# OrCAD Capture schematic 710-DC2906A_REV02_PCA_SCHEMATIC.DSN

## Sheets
1 PAGE2: company: ANALOG DEVICES; note: DEMO BOARD BILL OF MATERIALS; note: ISOLATED TRIPLE OUTPUT FLYBACK
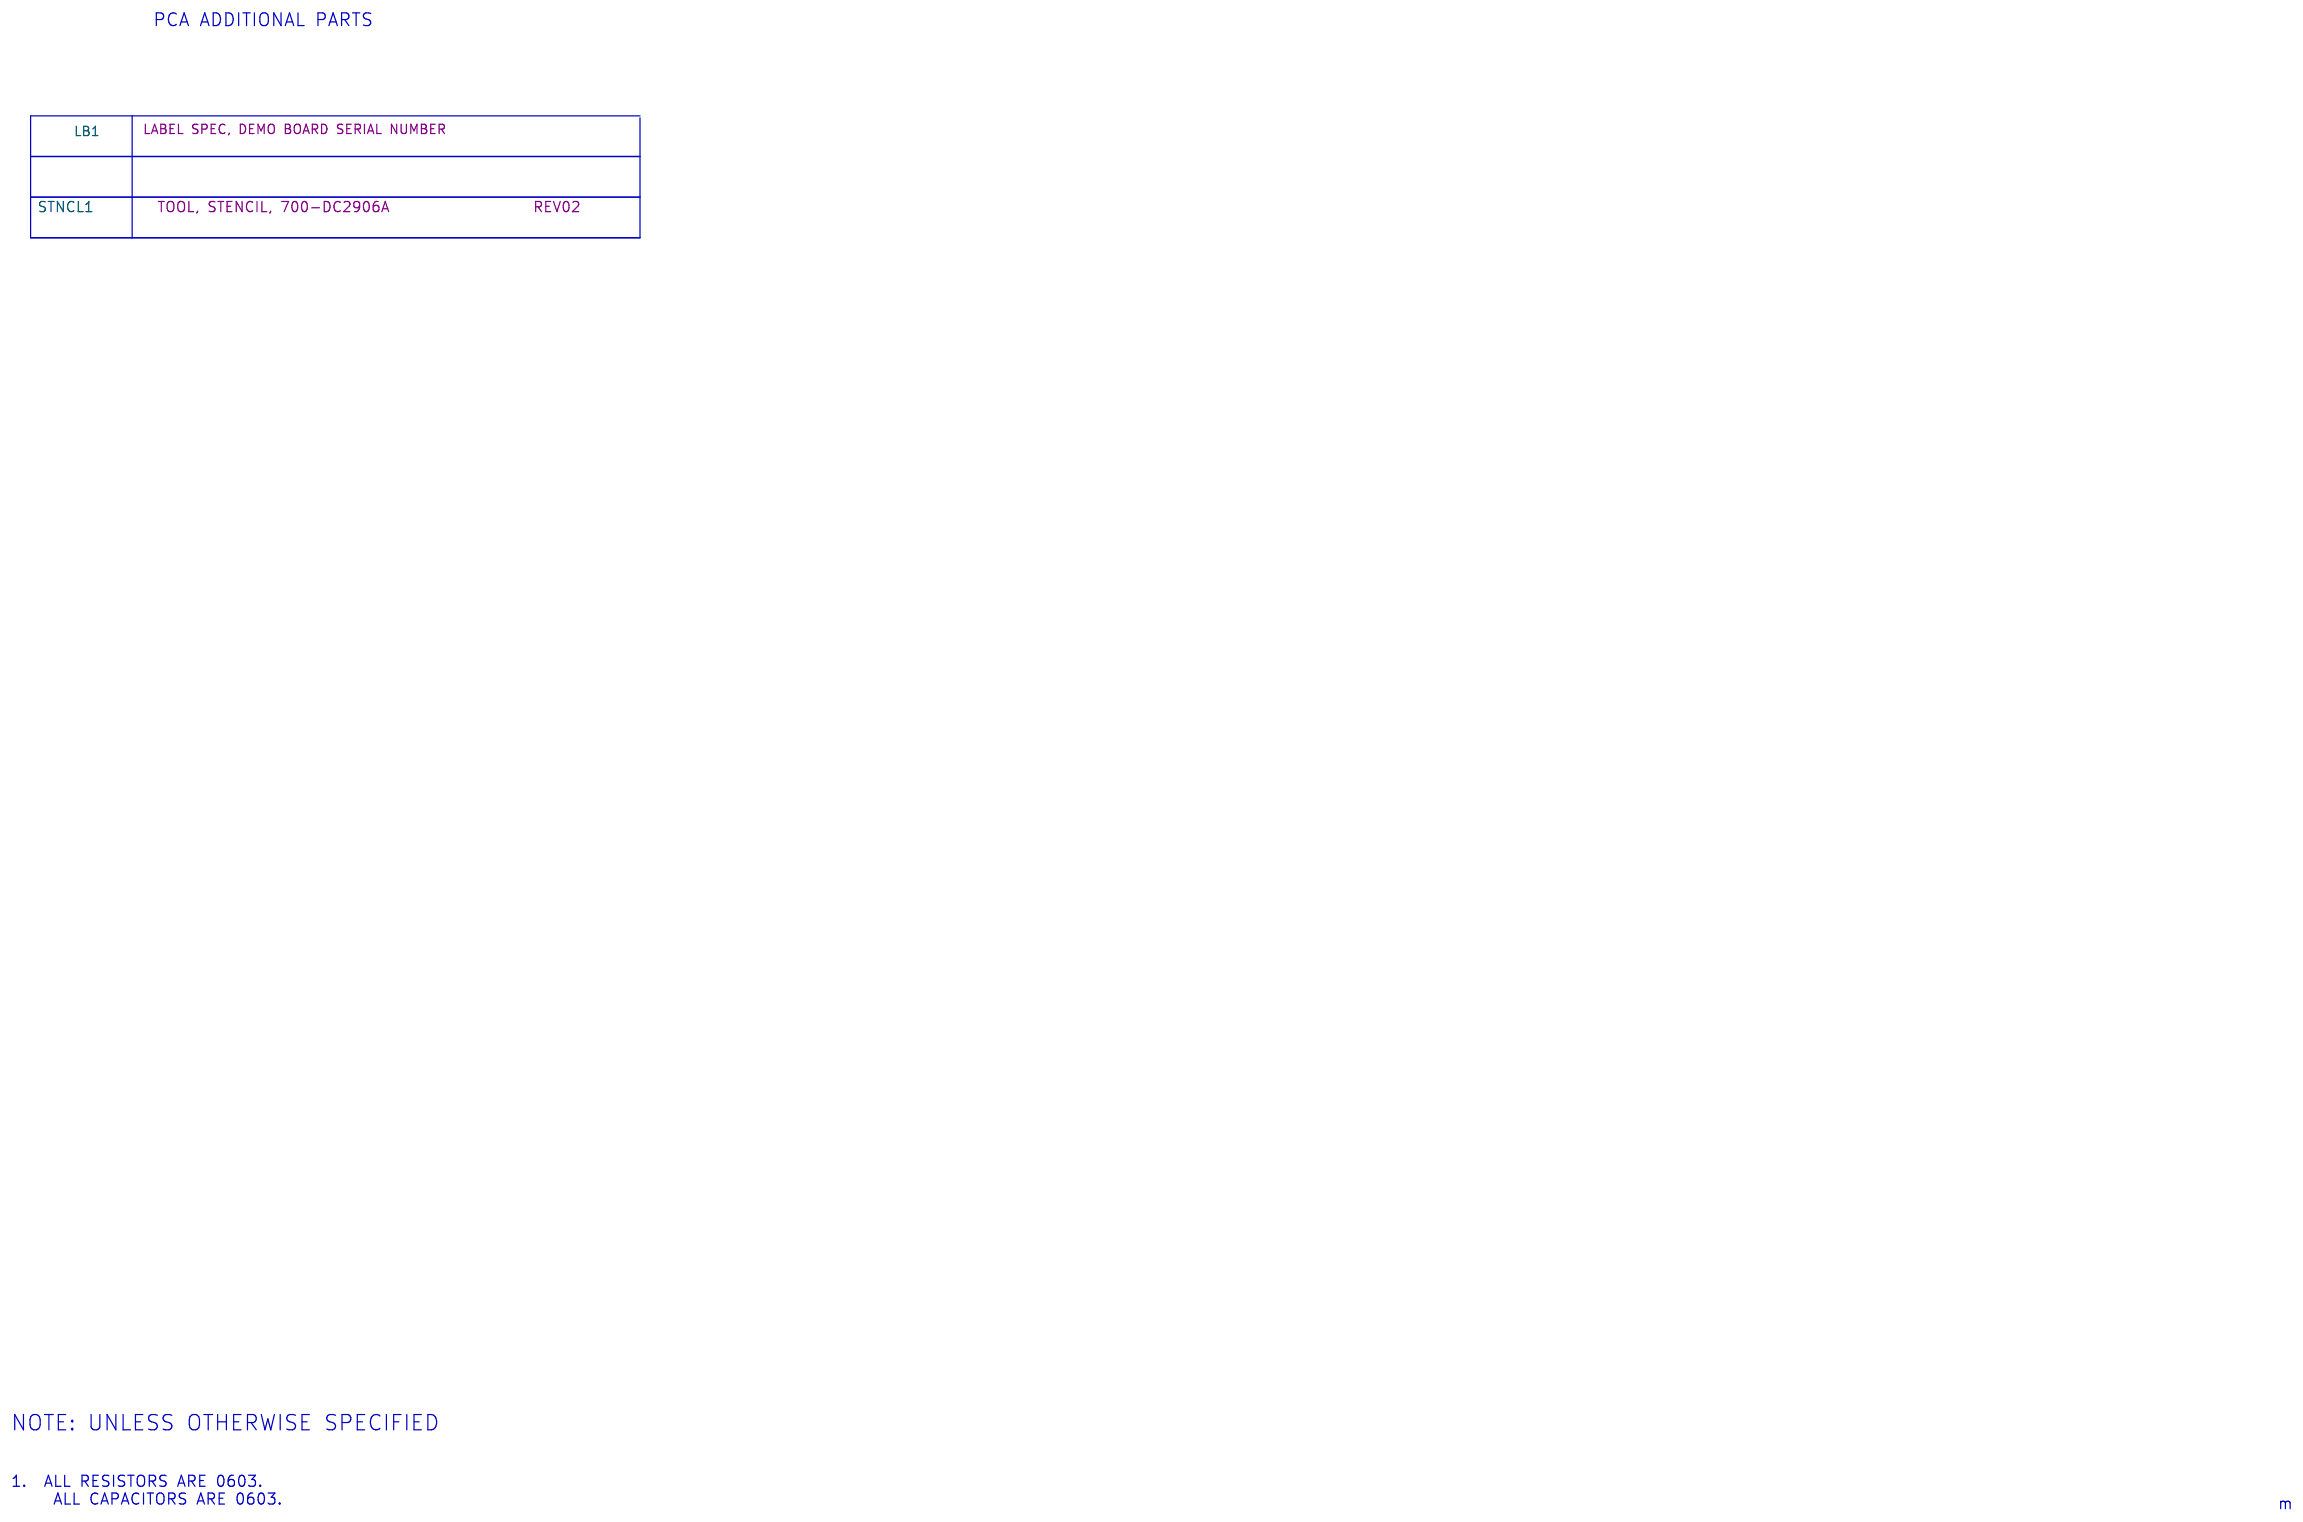
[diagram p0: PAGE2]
2 LT8302: size Custom
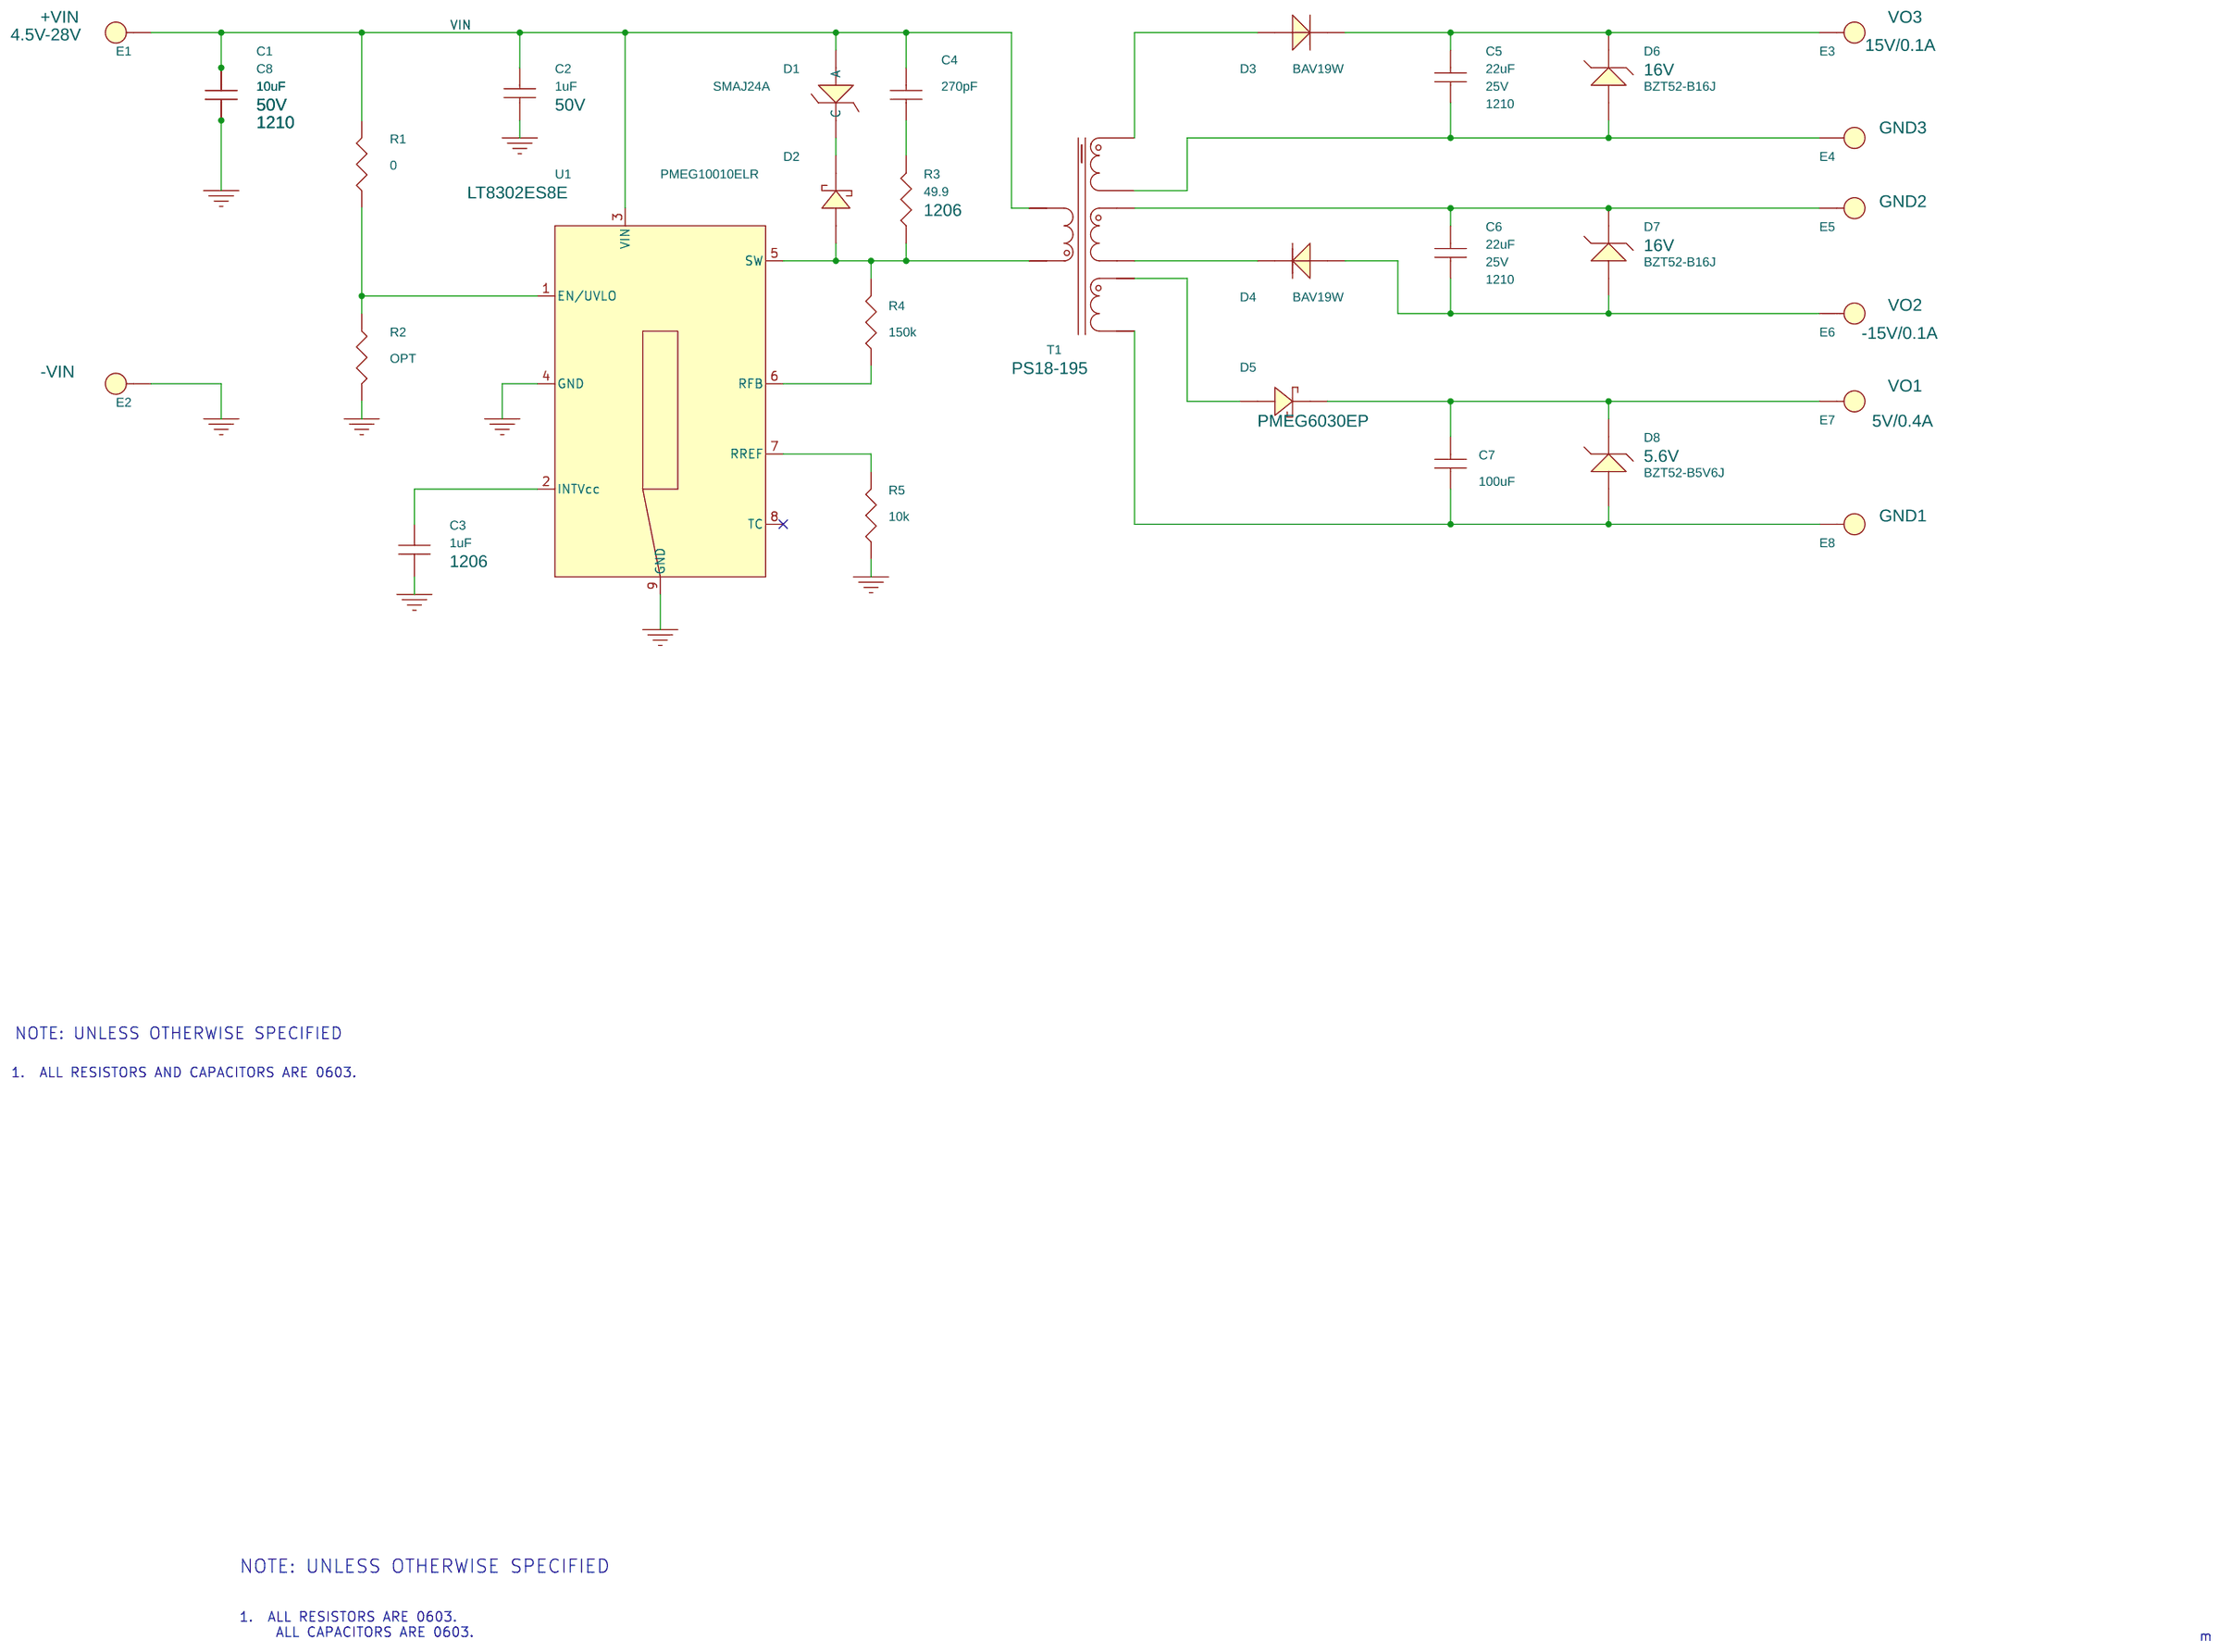
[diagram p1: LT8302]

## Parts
sheet LT8302
C1  10uF  [CC1210N]
C2  1uF  [CC0603N]
C3  1uF  [CC1206N]
C4  270pF  [CC0603N]
C5  22uF  [CC1210N]
C6  22uF  [CC1210N]
C7  100uF  [CC1210N]
C8  10uF  [CC1210N]
D1  SMAJ24A  [SMA-N]
D2  PMEG10010ELR  [NXP-SOD-123W]
D3  BAV19W  [SOD-123N]
D4  BAV19W  [SOD-123N]
D5  PMEG6030EP,115  [SOD-128N]
D6  BZT52-B16J  [SOD-123N]
D7  BZT52-B16J  [SOD-123N]
D8  BZT52-B5V6J  [SOD-123N]
E1  TEST POINT  [MILLMAX2308]
E2  TEST POINT  [MILLMAX2308]
E3  TEST POINT  [MILLMAX2308]
E4  TEST POINT  [MILLMAX2308]
E5  TEST POINT  [MILLMAX2308]
E6  TEST POINT  [MILLMAX2308]
E7  TEST POINT  [MILLMAX2308]
E8  TEST POINT  [MILLMAX2308]
PCB1  PCB, DC2906A
R1  0  [CR0603N]
R2  OPT  [CR0603N]
R3  49.9  [CR1206N]
R4  150k  [CR0603N]
R5  10k  [CR0603N]
T1  PS18-195  [TRAN-SUMIDA-CEP1313B]
U1  LT8302-S8E  [LTC-S8E-8-1857]
sheet PAGE2
LB1  LABEL  [895-0154_REV01]
STNCL1  TOOL, STENCIL, 700-DC2906A

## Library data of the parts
C1 C8 = CAP: CAP.,10uF,X7R,50V,10%,1210, NO SUBS. ALLOWED; CLASS: DISCRETE; Dielectric Type: X7R; FPLIST: CC1210N,CC1210L,CC1210M; Inventory Qty: 54166; Manufacturer: MURATA; Manufacturer PN: GRM32ER71H106KA12L; PART_NUMBER: 150-3043; Package Size: 1210; Package Type: SMD; Rated Voltage: 50V; Tolerance: 10%
C2 = CAP: CAP.,1uF,X7R,50V,10%,0603; CLASS: DISCRETE; Dielectric Type: X7R; FPLIST: CC0603N,CC0603L,CC0603M; Inventory Qty: 9153; Manufacturer: AVX; Manufacturer PN: 06035C105KAT2A; PART_NUMBER: 150-2333; Package Size: 0603; Rated Voltage: 50V; Tolerance: 10%
C3 = CAP: CAP.,1uF,X7R,50V,10%,1206; CLASS: DISCRETE; Dielectric Type: X7R; FPLIST: CC1206N,CC1206L,CC1206M; Inventory Qty: 5029; Manufacturer: AVX; Manufacturer PN: 12065C105KAT2A; PART_NUMBER: 150-3089; Package Size: 1206; Rated Voltage: 50V; Tolerance: 10%
C4 = CAP: CAP.,270pF,C0G,100V,5%,0603; CLASS: DISCRETE; Dielectric Type: C0G; FPLIST: CC0603N,CC0603L,CC0603M; Inventory Qty: 15700; Manufacturer: AVX; Manufacturer PN: 06031A271JAT2A; PART_NUMBER: 150-2534; Package Size: 0603; Rated Voltage: 100V; Tolerance: 5%
C5 C6 = CAP: CAP.,22uF,X7R,25V,10%,1210; CLASS: DISCRETE; Dielectric Type: X7R; FPLIST: CC1210N,CC1210L,CC1210M; Inventory Qty: 13370; Manufacturer: AVX; Manufacturer PN: 12103C226KAT2A; PART_NUMBER: 150-3343; Package Size: 1210; Rated Voltage: 25V; Tolerance: 10%
C7 = CAP: CAP.,100uF,X5R,10V,20%,1210; CLASS: DISCRETE; Dielectric Type: X5R; FPLIST: CC1210N,CC1210L,CC1210M; Inventory Qty: 17650; Manufacturer: KEMET; Manufacturer PN: C1210C107M8PACTU; PART_NUMBER: 150-3234; Package Size: 1210; Rated Voltage: 10V; Tolerance: 20%
D1 = DIODE_TVS_B: DIODE,TVS, SINGLE, UNI-DIRECT,24V,400W,SMA; CLASS: DISCRETE; FPLIST: SMA-N,SMA-L,SMA-M,SMA; Inventory Qty: 2500; Manufacturer: DIODES INC.; Manufacturer PN: SMAJ24A-13-F; Max Forward Current or Rated Power: 400W; PART_NUMBER: 210-0121; Package Size: SMA; Package Type: SMA; Rated Voltage or Zener Voltage: 24V
D2 = DIODE_SCHOTTKY_A_ALT: DIODE,SCHOTTKY,100V,1A,SOD-123W,AEC-Q101; CLASS: DISCRETE; Inventory Qty: 200; Manufacturer: NEXPERIA; PART_NUMBER: 210-0325; Package Type: SOD-123W; Rated Voltage or Zener Voltage: 100V
D3 D4 = DIODE_A_ALT: DIODE,SWITCHING,100V,250mW,SOD-123; CLASS: DISCRETE; FPLIST: SOD-123N,SOD-123L,SOD-123M; Inventory Qty: 0; Manufacturer: DIODES INC.; Manufacturer PN: BAV19W-7-F; PART_NUMBER: 210-0402; Package Type: SOD-123; Rated Voltage or Zener Voltage: 100V
D5 = DIODE_SCHOTTKY_A_ALT: DIODE,SCHOTTKY,60V,3A,SOD-128,AEC-Q101; 1st_Part_Field: PMEG6030EP; CLASS: DISCRETE; FPLIST: SOD-128N,SOD-128L,SOD-128M; Inventory Qty: 300; Manufacturer: NEXPERIA; Max Forward Current or Rated Power: 3A; PART_NUMBER: 210-0239; Package Size: SOD-128; Package Type: SOD-128; Rated Voltage or Zener Voltage: 60V
D6 D7 = ZENER_ALT: DIODE,ZENER,16V,590mW,SOD-123,AEC-Q101; 1st_Part_Field: 16V; CLASS: DISCRETE; FPLIST: SOD-123N,SOD-123M,SOD-123L; Inventory Qty: 0; Manufacturer: NEXPERIA; PART_NUMBER: 210-0403; Package Size: SOD-123; Package Type: SOD-123; Rated Voltage or Zener Voltage: 16V
D8 = ZENER_ALT: DIODE,ZENER,5.6V,590mW,SOD-123,AEC-Q101; 1st_Part_Field: 5.6V; CLASS: DISCRETE; FPLIST: SOD-123N,SOD-123M,SOD-123L; Inventory Qty: 0; Manufacturer: NEXPERIA; PART_NUMBER: 210-0404; Package Size: SOD-123; Package Type: SOD-123; Rated Voltage or Zener Voltage: 5.6V
E1 = TEST_POINT_.156_MILL-MAX_2308: TEST POINT,TURRET,0.064",MTG. HOLE; CLASS: IO; Inventory Qty: 798884; Manufacturer: MILL-MAX; Manufacturer PN: 2308-2-00-80-00-00-07-0; PART_FIELD_1: 4.5V-28V; PART_FIELD_2: +VIN; PART_NUMBER: 260-0004
E2 = TEST_POINT_.156_MILL-MAX_2308: TEST POINT,TURRET,0.064",MTG. HOLE; CLASS: IO; Inventory Qty: 798884; Manufacturer: MILL-MAX; Manufacturer PN: 2308-2-00-80-00-00-07-0; PART_FIELD_1: -VIN; PART_NUMBER: 260-0004
E3 = TEST_POINT_.156_MILL-MAX_2308: TEST POINT,TURRET,0.064",MTG. HOLE; CLASS: IO; Inventory Qty: 798884; Manufacturer: MILL-MAX; Manufacturer PN: 2308-2-00-80-00-00-07-0; PART_FIELD_1: VO3; PART_FIELD_2: 15V/0.1A; PART_NUMBER: 260-0004
E4 = TEST_POINT_.156_MILL-MAX_2308: TEST POINT,TURRET,0.064",MTG. HOLE; CLASS: IO; Inventory Qty: 798884; Manufacturer: MILL-MAX; Manufacturer PN: 2308-2-00-80-00-00-07-0; PART_FIELD_1: GND3; PART_NUMBER: 260-0004
E5 = TEST_POINT_.156_MILL-MAX_2308: TEST POINT,TURRET,0.064",MTG. HOLE; CLASS: IO; Inventory Qty: 798884; Manufacturer: MILL-MAX; Manufacturer PN: 2308-2-00-80-00-00-07-0; PART_FIELD_1: GND2; PART_NUMBER: 260-0004
E6 = TEST_POINT_.156_MILL-MAX_2308: TEST POINT,TURRET,0.064",MTG. HOLE; CLASS: IO; Inventory Qty: 798884; Manufacturer: MILL-MAX; Manufacturer PN: 2308-2-00-80-00-00-07-0; PART_FIELD_1: VO2; PART_FIELD_2: -15V/0.1A; PART_NUMBER: 260-0004
E7 = TEST_POINT_.156_MILL-MAX_2308: TEST POINT,TURRET,0.064",MTG. HOLE; CLASS: IO; Inventory Qty: 798884; Manufacturer: MILL-MAX; Manufacturer PN: 2308-2-00-80-00-00-07-0; PART_FIELD_1: VO1; PART_FIELD_2: 5V/0.4A; PART_NUMBER: 260-0004
E8 = TEST_POINT_.156_MILL-MAX_2308: TEST POINT,TURRET,0.064",MTG. HOLE; CLASS: IO; Inventory Qty: 798884; Manufacturer: MILL-MAX; Manufacturer PN: 2308-2-00-80-00-00-07-0; PART_FIELD_1: GND1; PART_NUMBER: 260-0004
PCB1 = BLANK_PCB_PART: BOM Notes: REV02; CLASS: DISCRETE; Inventory Qty: 0; Manufacturer: EAGLE TECH. INC.; Manufacturer PN: 600-DC2906A; PART_NUMBER: 600-DC2906A
R1 = RES: RES.,0 OHM,1/10W,0603,AEC-Q200; CLASS: DISCRETE; FPLIST: CR0603N,CR0603L,CR0603M; Inventory Qty: 509372; Manufacturer: VISHAY; Manufacturer PN: CRCW06030000Z0EA; PART_NUMBER: 100-0009; Package Size: 0603; Rated Power: 1/10W
R2 = RES: RES., OPTION, 0603; CLASS: DISCRETE; FPLIST: CR0603N,CR0603L,CR0603M; PART_NUMBER: 100-2374; Package Size: 0603
R3 = RES: RES.,49.9 OHMS,1%,1/4W,1206,AEC-Q200; CLASS: DISCRETE; FPLIST: CR1206N,CR1206L,CR1206M; Inventory Qty: 31388; Manufacturer: NIC; Manufacturer PN: NRC12F49R9TRF; PART_NUMBER: 100-2791; Package Size: 1206; Rated Power: 1/4W; Temperature Coefficient: 100ppm/C; Tolerance: 1%
R4 = RES: RES.,150k OHMS,1%,1/10W,0603; CLASS: DISCRETE; FPLIST: CR0603N,CR0603L,CR0603M; Inventory Qty: 12926; Manufacturer: PANASONIC; Manufacturer PN: ERJ3EKF1503V; PART_NUMBER: 100-2438; Package Size: 0603; Rated Power: 1/10W; Temperature Coefficient: 100ppm/C; Tolerance: 1%
R5 = RES: RES.,10k OHMS,0.1%,1/8W,0603,ANTI-SULFUR, AEC-Q200; CLASS: DISCRETE; FPLIST: CR0603N,CR0603L,CR0603M; Inventory Qty: 10500; Manufacturer: VISHAY; Manufacturer PN: TNPW060310K0BEEA; PART_NUMBER: 100-2059; Package Size: 0603; Rated Power: 1/8W; Temperature Coefficient: +/-25ppm; Tolerance: 0.1%
T1 = SUMIDA-CEP1313B: XFMR,FLYBACK,9V-28VIN,15.2 x 14.0 mm SMD,2*15VOUT/0.1A, 5VOUT/0.4A; CLASS: DISCRETE; Inventory Qty: 0; Manufacturer: SUMIDA; PART_NUMBER: 410-0107
U1 = LT8302_8304-S8E-X: IC,Isolated Flyback Converter,SOIC-8; 1st_Part_Field: LT8302ES8E; CLASS: IC; Inventory Qty: 75; Manufacturer: LINEAR TECH.; Manufacturer PN: LT8302ES8E#PBF; PART_NUMBER: LT8302ES8E#PBF; Package Type: SOIC-8
LB1 = BLANK_LABEL: LABEL SPEC, DEMO BOARD SERIAL NUMBER; Inventory Qty: 0; Manufacturer: BRADY; Manufacturer PN: THT-96-717-10; PART_NUMBER: 895-0154
STNCL1 = BLANK_STENCIL_PART: BOM Notes: REV02; CLASS: DISCRETE; Inventory Qty: 0; Manufacturer: LINEAR TECH.; Manufacturer PN: 830-DC2906A; PART_NUMBER: 830-DC2906A

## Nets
GND: C1.1 C2.2 C3.2 C8.1 E2.1(A) R2.1 R5.2 U1.4(GND) U1.9(GND)
VIN: C1.2 C2.1 C4.2 C8.2 D1.2(A) E1.1(A) R1.1 T1.9 T1.10 U1.3(VIN)
N16958277: C5.2 D3.1(C) D6.1(C) E3.1(A)
N16958357: D2.2(A) R3.2 R4.1 T1.11 T1.12 U1.5(SW)
N16958363: D3.2(A) T1.1
N16958391: C5.1 D6.2(A) E4.1(A) T1.2
N16958426: R4.2 U1.6(RFB)
N16958468: R5.1 U1.7(RREF)
N16958490: C3.1 U1.2(INTVcc)
N16958528: R1.2 R2.2 U1.1(EN/UVLO)
N16973060: C4.1 R3.1
N16997214: D1.1(C) D2.1(C)
N17006557: C6.2 D7.1(C) E5.1(A) T1.3
N17006649: D4.1(C) T1.4
N17006666: C6.1 D4.2(A) D7.2(A) E6.1(A)
N17006682: D5.2(A) T1.5 T1.6
N17006931: C7.1 D8.2(A) E8.1(A) T1.7 T1.8
N17006949: C7.2 D5.1(C) D8.1(C) E7.1(A)

Not connected (* = marked no-connect by the designer): U1 8(TC)*

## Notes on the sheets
sheet 1
- PCA ADDITIONAL PARTS
- NOTE: UNLESS OTHERWISE SPECIFIED
- 1.  ALL RESISTORS ARE 0603.
       ALL CAPACITORS ARE 0603.
- m
sheet 2
- NOTE: UNLESS OTHERWISE SPECIFIED
- 1.  ALL RESISTORS AND CAPACITORS ARE 0603.
- NOTE: UNLESS OTHERWISE SPECIFIED
- 1.  ALL RESISTORS ARE 0603.
       ALL CAPACITORS ARE 0603.
- m
